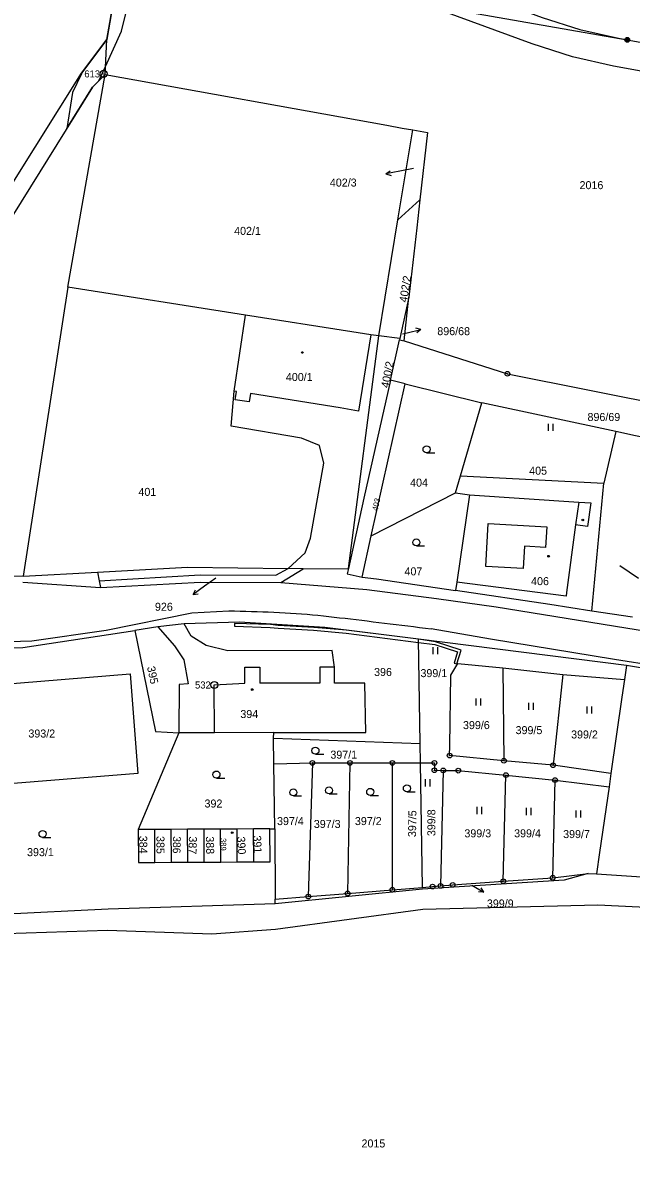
# Model space of a CAD drawing. Extents: x -504988 to -494607, y -1123820 to -1114018.
# Drawn here: x -500642.7 to -500513.4, y -1121156.5 to -1120913.2 of the extents above; entities that cross this region are included whole.
import ezdxf

# ---------------------------------------------------------------- set-up
doc = ezdxf.new("R2010")
doc.units = 0
for name, color, linetype in [('Hranice parcel', 7, 'Continuous'), ('Parcelní čísla', 7, 'Continuous'), ('Pop  PČ popisy', 7, 'Continuous'), ('Poz předměty', 7, 'Continuous'), ('Vnitřní kresba', 7, 'Continuous'), ('Věcná břemena k části', 7, 'Continuous'), ('Značky bodu BP', 7, 'Continuous'), ('Značky budov', 7, 'Continuous'), ('Značky kultur', 7, 'Continuous')]:
    doc.layers.add(name, color=color, linetype=linetype)

msp = doc.modelspace()

# ---------------------------------------------------------------- linework, layer by layer
at = {"layer": 'Hranice parcel'}
for p, q in [((-500624.9, -1120916.79), (-500620.47, -1120890.99)), ((-500625.28, -1120924.23), (-500624.9, -1120916.79)), ((-500633.18, -1120969.39), (-500625.28, -1120924.23)), ((-500563.02, -1120955.08), (-500559.87, -1120935.98)), ((-500558.33, -1120950.8), (-500563.02, -1120955.08)), ((-500567.08, -1120979.72), (-500563.02, -1120955.08)), ((-500633.18, -1120969.39), (-500642.71, -1121030.76)), ((-500595.39, -1120975.3), (-500633.18, -1120969.39)), ((-500560.66, -1120971.53), (-500562.61, -1120980.26)), ((-500561.67, -1120980.8), (-500560.66, -1120971.53)), ((-500573.51, -1121029.13), (-500567.08, -1120979.72)), ((-500562.61, -1120980.26), (-500567.08, -1120979.72)), ((-500564.59, -1120989.12), (-500562.69, -1120980.6)), ((-500562.61, -1120980.26), (-500562.69, -1120980.6)), ((-500562.69, -1120980.6), (-500561.67, -1120980.8)), ((-500568.68, -1121022.21), (-500561.45, -1120989.9)), ((-500561.45, -1120989.9), (-500564.59, -1120989.12)), ((-500561.45, -1120989.9), (-500545.17, -1120993.98)), ((-500549.69, -1121009.43), (-500545.17, -1120993.98)), ((-500516.66, -1121000.06), (-500545.17, -1120993.98)), ((-500516.66, -1121000.06), (-500519.27, -1121011)), ((-500550.76, -1121013.08), (-500549.69, -1121009.43)), ((-500549.69, -1121009.43), (-500519.27, -1121011)), ((-500568.68, -1121022.21), (-500550.76, -1121013.08)), ((-500521.79, -1121038.18), (-500519.27, -1121011)), ((-500570.64, -1121031), (-500568.68, -1121022.21)), ((-500642.71, -1121030.76), (-500626.85, -1121029.9)), ((-500583.15, -1121029.22), (-500586.36, -1121029.11)), ((-500583.15, -1121029.22), (-500573.51, -1121029.13)), ((-500513.13, -1121039.51), (-500521.79, -1121038.18)), ((-500614.03, -1121041.57), (-500618.97, -1121042.32)), ((-500608.44, -1121040.9), (-500614.03, -1121041.57)), ((-500558.29, -1121066.33), (-500558.64, -1121044.18)), ((-500514.41, -1121049.75), (-500558.64, -1121044.18)), ((-500540.68, -1121050.26), (-500527.99, -1121051.68)), ((-500540.68, -1121050.26), (-500540.49, -1121070)), ((-500527.99, -1121051.68), (-500530.04, -1121070.93)), ((-500527.99, -1121051.68), (-500514.83, -1121052.7)), ((-500514.41, -1121049.75), (-500514.83, -1121052.7)), ((-500479.4, -1121055.39), (-500514.41, -1121049.75)), ((-500514.83, -1121052.7), (-500515.38, -1121056.46)), ((-500515.38, -1121056.46), (-500517.72, -1121072.72)), ((-500609.57, -1121064.08), (-500618.21, -1121084.59)), ((-500589.43, -1121065.18), (-500589.36, -1121064.01)), ((-500589.37, -1121070.65), (-500589.43, -1121065.18)), ((-500589.43, -1121065.18), (-500558.29, -1121066.33)), ((-500558.22, -1121070.44), (-500558.29, -1121066.33)), ((-500589.37, -1121070.65), (-500581.2, -1121070.43)), ((-500589.21, -1121084.46), (-500589.37, -1121070.65)), ((-500581.2, -1121070.43), (-500582.08, -1121098.84)), ((-500581.2, -1121070.43), (-500573.2, -1121070.45)), ((-500573.2, -1121070.45), (-500573.71, -1121098.17)), ((-500573.2, -1121070.45), (-500564.2, -1121070.45)), ((-500564.2, -1121070.45), (-500558.22, -1121070.44)), ((-500564.19, -1121097.4), (-500564.2, -1121070.45)), ((-500557.81, -1121096.88), (-500558.22, -1121070.44)), ((-500530.04, -1121070.93), (-500540.49, -1121070)), ((-500517.72, -1121072.72), (-500530.04, -1121070.93)), ((-500553.38, -1121072.04), (-500553.95, -1121096.57)), ((-500540.62, -1121095.59), (-500540.07, -1121073.02)), ((-500540.07, -1121073.02), (-500529.61, -1121074.08)), ((-500517.72, -1121072.72), (-500518.13, -1121075.56)), ((-500530.09, -1121094.83), (-500529.61, -1121074.08)), ((-500529.61, -1121074.08), (-500518.13, -1121075.56)), ((-500614.71, -1121084.58), (-500618.21, -1121084.59)), ((-500611.21, -1121084.56), (-500614.71, -1121084.58)), ((-500614.67, -1121091.58), (-500614.71, -1121084.58)), ((-500607.71, -1121084.54), (-500611.21, -1121084.56)), ((-500611.17, -1121091.56), (-500611.21, -1121084.56)), ((-500604.21, -1121084.53), (-500607.71, -1121084.54)), ((-500607.67, -1121091.54), (-500607.71, -1121084.54)), ((-500600.71, -1121084.51), (-500604.21, -1121084.53)), ((-500604.17, -1121091.53), (-500604.21, -1121084.53)), ((-500597.21, -1121084.5), (-500600.71, -1121084.51)), ((-500600.67, -1121091.51), (-500600.71, -1121084.51)), ((-500593.71, -1121084.48), (-500597.21, -1121084.5)), ((-500597.17, -1121091.49), (-500597.21, -1121084.5)), ((-500590.21, -1121084.46), (-500593.71, -1121084.48)), ((-500593.67, -1121091.48), (-500593.71, -1121084.48)), ((-500590.21, -1121084.46), (-500589.21, -1121084.46)), ((-500589.21, -1121084.46), (-500589.1, -1121099.41)), ((-500614.67, -1121091.58), (-500611.17, -1121091.56)), ((-500611.17, -1121091.56), (-500607.67, -1121091.54)), ((-500607.67, -1121091.54), (-500604.17, -1121091.53)), ((-500604.17, -1121091.53), (-500600.67, -1121091.51)), ((-500600.67, -1121091.51), (-500597.17, -1121091.49)), ((-500597.17, -1121091.49), (-500593.67, -1121091.48)), ((-500540.62, -1121095.59), (-500530.09, -1121094.83)), ((-500530.09, -1121094.83), (-500522.58, -1121093.91)), ((-500522.58, -1121093.91), (-500520.79, -1121094.02)), ((-500582.08, -1121098.84), (-500573.71, -1121098.17)), ((-500573.71, -1121098.17), (-500564.19, -1121097.4)), ((-500564.19, -1121097.4), (-500557.81, -1121096.88)), ((-500589.1, -1121099.41), (-500582.08, -1121098.84)), ((-500589.09, -1121100.4), (-500589.1, -1121099.41))]:
    msp.add_line(p, q, dxfattribs=at)
for points in [[(-500764.98, -1120898.32), (-500631.41, -1120885.98), (-500618.26, -1120885.7), (-500608.56, -1120886.58), (-500597.08, -1120888.85), (-500587.15, -1120891.94), (-500532.37, -1120912.08), (-500524.35, -1120914.64), (-500516.15, -1120916.5), (-500513.53, -1120917), (-500396.19, -1120938.19), (-500282.34, -1120959.31), (-500275.43, -1120961.08), (-500094.63, -1121020.61), (-499913.83, -1121080.14), (-499909.87, -1121081.53), (-499905.97, -1121083.08), (-499793.8, -1121130.28), (-499791.45, -1121131.2), (-499789.49, -1121131.83)], [(-500481.13, -1120928.92), (-500517.21, -1120922.4), (-500525.93, -1120920.43), (-500534.44, -1120917.72), (-500589.22, -1120897.57), (-500597.01, -1120895.29), (-500604.68, -1120893.47), (-500611.82, -1120892.14), (-500620.47, -1120890.99)], [(-500687.09, -1121019.98), (-500659.52, -1120970.53), (-500630.25, -1120923.93), (-500624.9, -1120916.79)], [(-500625.28, -1120924.23), (-500627.91, -1120926.88), (-500656.36, -1120972.42), (-500691.37, -1121033.75)], [(-500625.28, -1120924.23), (-500565.35, -1120934.99), (-500562.14, -1120935.57), (-500559.87, -1120935.98)], [(-500559.87, -1120935.98), (-500556.72, -1120936.54), (-500558.33, -1120950.8)], [(-500558.33, -1120950.8), (-500559, -1120956.76), (-500560.66, -1120971.53)], [(-500586.36, -1121029.11), (-500582.7, -1121025.8), (-500581.62, -1121022.67), (-500578.76, -1121006.77), (-500579.7, -1121002.99), (-500583.5, -1121001.43), (-500598.48, -1120998.91), (-500597.83, -1120991.44), (-500595.39, -1120975.3)], [(-500567.08, -1120979.72), (-500568.78, -1120979.52), (-500572.78, -1120978.84), (-500595.39, -1120975.3)], [(-500561.67, -1120980.8), (-500539.74, -1120987.79), (-500504.48, -1120994.81)], [(-500564.59, -1120989.12), (-500570.24, -1121014.17), (-500573.51, -1121029.13)], [(-500506.98, -1121002.13), (-500512.53, -1121000.94), (-500516.66, -1121000.06)], [(-500550.76, -1121013.08), (-500547.79, -1121013.52), (-500550.51, -1121032.04), (-500550.77, -1121033.82)], [(-500689.76, -1121033.75), (-500661.6, -1121029.96), (-500654.12, -1121030.57), (-500642.71, -1121030.76)], [(-500626.85, -1121029.9), (-500607.74, -1121028.86), (-500586.36, -1121029.11)], [(-500626.85, -1121029.9), (-500626.51, -1121031.75), (-500626.25, -1121033.18), (-500605.01, -1121032.04), (-500587.93, -1121032.15), (-500583.15, -1121029.22)], [(-500573.51, -1121029.13), (-500573.77, -1121030.3), (-500570.64, -1121031)], [(-500570.64, -1121031), (-500567.54, -1121031.33), (-500550.77, -1121033.82)], [(-500521.79, -1121038.18), (-500530.71, -1121036.82), (-500550.77, -1121033.82)], [(-500668.7, -1121046.08), (-500642.76, -1121045.92), (-500618.97, -1121042.32)], [(-500618.97, -1121042.32), (-500614.53, -1121063.76), (-500609.57, -1121064.08)], [(-500614.03, -1121041.57), (-500610.51, -1121045.56), (-500608.52, -1121048.57), (-500607.58, -1121053.62), (-500609.52, -1121053.78), (-500609.57, -1121064.08)], [(-500558.64, -1121044.18), (-500578.56, -1121041.67), (-500596.71, -1121040.56), (-500608.44, -1121040.9)], [(-500589.36, -1121064.01), (-500569.85, -1121063.98), (-500570.07, -1121053.48), (-500576.51, -1121053.48), (-500576.51, -1121050.07), (-500576.97, -1121046.59), (-500599.18, -1121046.66), (-500603.8, -1121045.48), (-500606.96, -1121043.54), (-500608.44, -1121040.9)], [(-500540.49, -1121070), (-500552.02, -1121068.9), (-500551.98, -1121066.84), (-500551.73, -1121051.81), (-500550.27, -1121049.31), (-500540.68, -1121050.26)], [(-500619.93, -1121051.53), (-500618.27, -1121072.71), (-500656.27, -1121075.76), (-500657.98, -1121054.66), (-500619.93, -1121051.53)], [(-500589.36, -1121064.01), (-500602.01, -1121064.03), (-500609.57, -1121064.08)], [(-500558.22, -1121070.44), (-500555.24, -1121070.44), (-500555.26, -1121072.01), (-500553.38, -1121072.04)], [(-500553.38, -1121072.04), (-500550.18, -1121072.09), (-500540.07, -1121073.02)], [(-500518.13, -1121075.56), (-500520.13, -1121089.47), (-500520.79, -1121094.02)], [(-500618.21, -1121084.59), (-500618.17, -1121091.59), (-500614.67, -1121091.58)], [(-500593.67, -1121091.48), (-500590.17, -1121091.46), (-500590.21, -1121084.46)], [(-500522.58, -1121093.91), (-500527.7, -1121095.32), (-500557.8, -1121097.25), (-500589.09, -1121100.4)], [(-500553.95, -1121096.57), (-500551.36, -1121096.36), (-500540.62, -1121095.59)], [(-500520.79, -1121094.02), (-500502.67, -1121095.18), (-500501.61, -1121095.25), (-500492.78, -1121096.41), (-500478.14, -1121101.05)], [(-500557.81, -1121096.88), (-500555.64, -1121096.71), (-500553.95, -1121096.57)], [(-500453.45, -1121120.1), (-500479.67, -1121107.66), (-500495.2, -1121102.84), (-500507.32, -1121101.3), (-500520.55, -1121100.68), (-500557.7, -1121101.61), (-500589.02, -1121105.86), (-500602.59, -1121106.82), (-500624.72, -1121106.08), (-500646.33, -1121106.76), (-500655.09, -1121112.32), (-500660.29, -1121119.96), (-500660.92, -1121120.88), (-500668.64, -1121133.13), (-500674.71, -1121144.91), (-500681.84, -1121162.26), (-500689.12, -1121188.67)], [(-500589.09, -1121100.4), (-500624.6, -1121101.5), (-500647.48, -1121102.68)]]:
    msp.add_lwpolyline(points, dxfattribs=at)
at = {"layer": 'Pop  PČ popisy'}
for p, q in [((-500565.56, -1120945.34), (-500564.67, -1120944.66)), ((-500562.61, -1120944.77), (-500565.56, -1120945.34)), ((-500559.67, -1120944.2), (-500562.61, -1120944.77)), ((-500565.56, -1120945.34), (-500564.48, -1120945.64)), ((-500562.07, -1120979.33), (-500561.06, -1120979.08)), ((-500561.06, -1120979.08), (-500558.15, -1120978.35)), ((-500558.15, -1120978.35), (-500559.24, -1120978.11)), ((-500558.15, -1120978.35), (-500559, -1120979.08)), ((-500515.83, -1121028.51), (-500511.9, -1121031.19)), ((-500601.7, -1121031.17), (-500604.12, -1121032.93)), ((-500604.12, -1121032.93), (-500606.55, -1121034.69)), ((-500606.55, -1121034.69), (-500606.03, -1121033.7)), ((-500606.55, -1121034.69), (-500605.44, -1121034.51)), ((-500547.33, -1121096.4), (-500544.73, -1121097.9)), ((-500544.73, -1121097.9), (-500545.85, -1121097.83)), ((-500544.73, -1121097.9), (-500545.35, -1121096.97))]:
    msp.add_line(p, q, dxfattribs=at)
at = {"layer": 'Poz předměty'}
for p, q in [((-500627.14, -1120897.09), (-500514.25, -1120916.84)), ((-500514.25, -1120916.84), (-500396.18, -1120938.19))]:
    msp.add_line(p, q, dxfattribs=at)
for radius in [0.5, 0.4, 0.3, 0.2, 0.1]:
    msp.add_circle((-500514.25, -1120916.84), radius, dxfattribs=at)
at = {"layer": 'Vnitřní kresba'}
for p, q in [((-500568.78, -1120979.52), (-500571.38, -1120995.7)), ((-500597.32, -1120991.52), (-500597.83, -1120991.44)), ((-500597.6, -1120993.28), (-500597.32, -1120991.52)), ((-500594.61, -1120993.76), (-500597.6, -1120993.28)), ((-500594.34, -1120992), (-500594.61, -1120993.76)), ((-500575.32, -1120995), (-500594.34, -1120992)), ((-500571.38, -1120995.7), (-500575.32, -1120995)), ((-500547.79, -1121013.52), (-500524.57, -1121015.06)), ((-500524.57, -1121015.06), (-500525.24, -1121019.87)), ((-500524.57, -1121015.06), (-500522, -1121015.23)), ((-500522, -1121015.23), (-500522.71, -1121020.2)), ((-500544.3, -1121028.74), (-500543.82, -1121019.61)), ((-500543.82, -1121019.61), (-500531.39, -1121020.27)), ((-500531.39, -1121020.27), (-500531.63, -1121024.67)), ((-500525.24, -1121019.87), (-500527.16, -1121034.25)), ((-500522.71, -1121020.2), (-500525.24, -1121019.87)), ((-500536.14, -1121024.43), (-500536.39, -1121029.16)), ((-500531.63, -1121024.67), (-500536.14, -1121024.43)), ((-500588.98, -1121030.59), (-500586.36, -1121029.11)), ((-500536.39, -1121029.16), (-500544.3, -1121028.74)), ((-500642.76, -1121032.04), (-500626.25, -1121033.18)), ((-500626.51, -1121031.75), (-500605.06, -1121030.47)), ((-500605.06, -1121030.47), (-500588.98, -1121030.59)), ((-500587.93, -1121032.15), (-500569.64, -1121033.58)), ((-500527.26, -1121035.03), (-500550.51, -1121032.04)), ((-500569.64, -1121033.58), (-500554.83, -1121035.49)), ((-500527.16, -1121034.25), (-500527.26, -1121035.03)), ((-500554.83, -1121035.49), (-500542.14, -1121037.31)), ((-500542.14, -1121037.31), (-500514.53, -1121041.74)), ((-500625.05, -1121042.22), (-500606.8, -1121038.58)), ((-500606.8, -1121038.58), (-500598.97, -1121038.11)), ((-500640.83, -1121044.49), (-500625.05, -1121042.22)), ((-500543.34, -1121044.15), (-500555.91, -1121041.96)), ((-500514.53, -1121041.74), (-500462.1, -1121050.16)), ((-500655.7, -1121044.96), (-500640.83, -1121044.49)), ((-500516.96, -1121048.51), (-500543.34, -1121044.15)), ((-500463.1, -1121056.99), (-500516.96, -1121048.51)), ((-500595.54, -1121053.49), (-500595.54, -1121050.12)), ((-500595.54, -1121050.12), (-500592.4, -1121050.12)), ((-500592.4, -1121050.12), (-500592.4, -1121053.49)), ((-500602.04, -1121053.89), (-500595.54, -1121053.49)), ((-500602.01, -1121064.03), (-500602.04, -1121053.89))]:
    msp.add_line(p, q, dxfattribs=at)
for points in [[(-500598.97, -1121038.11), (-500597.77, -1121038.14), (-500596.55, -1121038.18), (-500595.35, -1121038.21), (-500594.15, -1121038.25), (-500592.94, -1121038.28), (-500591.75, -1121038.33), (-500590.56, -1121038.38), (-500589.36, -1121038.43), (-500588.18, -1121038.49), (-500587, -1121038.55), (-500585.82, -1121038.62), (-500584.65, -1121038.7), (-500583.49, -1121038.79), (-500582.32, -1121038.88), (-500581.17, -1121038.99), (-500580.03, -1121039.09), (-500578.86, -1121039.21), (-500577.72, -1121039.33), (-500576.57, -1121039.46), (-500575.4, -1121039.59), (-500574.24, -1121039.73), (-500573.08, -1121039.86), (-500571.89, -1121040.01), (-500570.71, -1121040.15), (-500569.52, -1121040.29), (-500568.3, -1121040.44), (-500567.09, -1121040.59), (-500565.88, -1121040.74), (-500564.64, -1121040.89), (-500563.41, -1121041.04), (-500562.17, -1121041.19), (-500560.91, -1121041.35), (-500559.67, -1121041.5), (-500558.42, -1121041.65), (-500557.16, -1121041.81), (-500555.91, -1121041.96)], [(-500576.51, -1121050.07), (-500579.58, -1121050.07), (-500579.58, -1121053.48), (-500592.4, -1121053.49)]]:
    msp.add_lwpolyline(points, dxfattribs=at)
at = {"layer": 'Věcná břemena k části'}
for points in [[(-500615.68, -1120873.77), (-500618.62, -1120885.71), (-500619.94, -1120891.06), (-500621.72, -1120898.29), (-500624.9, -1120916.79), (-500630.25, -1120923.93), (-500630.31, -1120924.03), (-500632.17, -1120928.06), (-500633.41, -1120935.69), (-500627.91, -1120926.88), (-500626.62, -1120925.58), (-500625.19, -1120922.48), (-500621.74, -1120915), (-500615.98, -1120891.59), (-500614.61, -1120886.03), (-500611.93, -1120875.15), (-500610.37, -1120871.36), (-500580.9, -1120800), (-500585.23, -1120800), (-500614.53, -1120870.98)], [(-500597.77, -1121041.42), (-500590.15, -1121041.67), (-500588.5, -1121041.85), (-500580.96, -1121042.27), (-500573.98, -1121042.87), (-500558.63, -1121044.85), (-500555.15, -1121045.3), (-500550.32, -1121046.87), (-500551.07, -1121049.24), (-500550.5, -1121049.42), (-500549.56, -1121046.48), (-500555.01, -1121044.71), (-500558.64, -1121044.18), (-500573.92, -1121042.27), (-500580.92, -1121041.67), (-500588.45, -1121041.25), (-500590.11, -1121041.07), (-500597.75, -1121040.82)]]:
    msp.add_lwpolyline(points, close=True, dxfattribs=at)
at = {"layer": 'Značky bodu BP'}
for centre, radius in [((-500625.58, -1120924.08), 0.75), ((-500625.58, -1120924.08), 0.03), ((-500539.74, -1120987.79), 0.5), ((-500539.74, -1120987.79), 0.0303), ((-500602.04, -1121053.89), 0.75), ((-500602.04, -1121053.89), 0.03), ((-500552.02, -1121068.9), 0.5), ((-500552.02, -1121068.9), 0.0303), ((-500581.2, -1121070.43), 0.5), ((-500581.2, -1121070.43), 0.0303), ((-500573.2, -1121070.45), 0.5), ((-500573.2, -1121070.45), 0.0303), ((-500564.2, -1121070.45), 0.5), ((-500564.2, -1121070.45), 0.0303), ((-500555.26, -1121072.01), 0.5), ((-500555.24, -1121070.44), 0.5), ((-500555.24, -1121070.44), 0.0303), ((-500553.38, -1121072.04), 0.5), ((-500540.49, -1121070), 0.5), ((-500540.49, -1121070), 0.0303), ((-500530.04, -1121070.93), 0.5), ((-500530.04, -1121070.93), 0.0303), ((-500555.26, -1121072.01), 0.0303), ((-500553.38, -1121072.04), 0.0303), ((-500550.18, -1121072.09), 0.5), ((-500550.18, -1121072.09), 0.0303), ((-500540.07, -1121073.02), 0.5), ((-500540.07, -1121073.02), 0.0303), ((-500529.61, -1121074.08), 0.5), ((-500529.61, -1121074.08), 0.0303), ((-500551.36, -1121096.36), 0.5), ((-500540.62, -1121095.59), 0.5), ((-500540.62, -1121095.59), 0.0303), ((-500530.09, -1121094.83), 0.5), ((-500530.09, -1121094.83), 0.0303), ((-500573.71, -1121098.17), 0.5), ((-500573.71, -1121098.17), 0.0303), ((-500564.19, -1121097.4), 0.5), ((-500564.19, -1121097.4), 0.0303), ((-500555.64, -1121096.71), 0.5), ((-500555.64, -1121096.71), 0.0303), ((-500553.95, -1121096.57), 0.5), ((-500553.95, -1121096.57), 0.0303), ((-500551.36, -1121096.36), 0.0303), ((-500582.08, -1121098.84), 0.5), ((-500582.08, -1121098.84), 0.0303)]:
    msp.add_circle(centre, radius, dxfattribs=at)
at = {"layer": 'Značky budov'}
for centre in [(-500583.34, -1120983.26), (-500523.72, -1121018.84), (-500530.99, -1121026.53), (-500593.99, -1121054.86), (-500598.24, -1121085.27)]:
    msp.add_circle(centre, 0.175, dxfattribs=at)
at = {"layer": 'Značky kultur'}
for p, q in [((-500530.98, -1120999.91), (-500530.98, -1120998.41)), ((-500529.98, -1120999.91), (-500529.98, -1120998.41)), ((-500556.92, -1121004.58), (-500555.17, -1121004.58)), ((-500559.09, -1121024.35), (-500557.34, -1121024.35)), ((-500555.55, -1121047.34), (-500555.55, -1121045.84)), ((-500554.55, -1121047.34), (-500554.55, -1121045.84)), ((-500546.37, -1121058.23), (-500546.37, -1121056.73)), ((-500545.37, -1121058.23), (-500545.37, -1121056.73)), ((-500535.16, -1121059.19), (-500535.16, -1121057.69)), ((-500534.16, -1121059.19), (-500534.16, -1121057.69)), ((-500522.78, -1121059.94), (-500522.78, -1121058.44)), ((-500521.78, -1121059.94), (-500521.78, -1121058.44)), ((-500580.54, -1121068.59), (-500578.79, -1121068.59)), ((-500601.59, -1121073.67), (-500599.84, -1121073.67)), ((-500557.15, -1121075.43), (-500557.15, -1121073.93)), ((-500556.15, -1121075.43), (-500556.15, -1121073.93)), ((-500585.23, -1121077.46), (-500583.48, -1121077.46)), ((-500577.65, -1121077.03), (-500575.9, -1121077.03)), ((-500568.9, -1121077.35), (-500567.15, -1121077.35)), ((-500561.11, -1121076.6), (-500559.36, -1121076.6)), ((-500546.15, -1121081.3), (-500546.15, -1121079.8)), ((-500545.15, -1121081.3), (-500545.15, -1121079.8)), ((-500535.69, -1121081.52), (-500535.69, -1121080.02)), ((-500534.69, -1121081.52), (-500534.69, -1121080.02)), ((-500525.13, -1121082.05), (-500525.13, -1121080.55)), ((-500524.13, -1121082.05), (-500524.13, -1121080.55)), ((-500638.55, -1121086.28), (-500636.8, -1121086.28))]:
    msp.add_line(p, q, dxfattribs=at)
for centre in [(-500556.92, -1121003.83), (-500559.09, -1121023.6), (-500580.54, -1121067.84), (-500601.59, -1121072.92), (-500585.23, -1121076.71), (-500577.65, -1121076.28), (-500568.9, -1121076.6), (-500561.11, -1121075.85), (-500638.55, -1121085.53)]:
    msp.add_circle(centre, 0.75, dxfattribs=at)

# ---------------------------------------------------------------- texts
at = {"layer": 'Parcelní čísla'}
for s, p in [('402/3', (-500577.48, -1120948.01)), ('2016', (-500524.4, -1120948.56)), ('402/1', (-500597.83, -1120958.27)), ('896/68', (-500554.64, -1120979.58)), ('400/1', (-500586.83, -1120989.31)), ('896/69', (-500522.71, -1120997.81)), ('405', (-500535.11, -1121009.22)), ('404', (-500560.42, -1121011.75)), ('401', (-500618.17, -1121013.72)), ('407', (-500561.62, -1121030.6)), ('406', (-500534.7, -1121032.68)), ('926', (-500614.66, -1121038.12)), ('396', (-500568.08, -1121051.98)), ('399/1', (-500558.22, -1121052.22)), ('394', (-500596.51, -1121060.91)), ('399/6', (-500549.18, -1121063.26)), ('393/2', (-500641.56, -1121065.05)), ('399/5', (-500538, -1121064.33)), ('399/2', (-500526.2, -1121065.25)), ('397/1', (-500577.37, -1121069.54)), ('392', (-500604.12, -1121079.92)), ('397/4', (-500588.71, -1121083.65)), ('397/3', (-500580.89, -1121084.26)), ('397/2', (-500572.16, -1121083.65)), ('399/3', (-500548.88, -1121086.25)), ('399/4', (-500538.31, -1121086.25)), ('399/7', (-500527.89, -1121086.41)), ('393/1', (-500641.85, -1121090.25)), ('399/9', (-500544.1, -1121101.15)), ('2015', (-500570.75, -1121152.13))]:
    msp.add_text(s, height=1.7, dxfattribs=at).set_placement(p)
for s, height, rotation, p in [('402/2', 1.7, 81, (-500561.07, -1120972.71)), ('400/2', 1.7, 79, (-500564.96, -1120990.9)), ('403', 1.2, 77, (-500567.34, -1121016.97)), ('395', 1.7, 282, (-500616.36, -1121050.1)), ('397/5', 1.7, 89, (-500559.17, -1121086.22)), ('399/8', 1.7, 90, (-500555.05, -1121086)), ('384', 1.7, 271, (-500618.02, -1121085.93)), ('385', 1.7, 270, (-500614.34, -1121085.98)), ('386', 1.646, 269, (-500610.81, -1121086)), ('387', 1.7, 268, (-500607.42, -1121086.03)), ('388', 1.7, 271, (-500603.83, -1121086.05)), ('391', 1.7, 273, (-500593.81, -1121085.9)), ('389', 1.2, 270, (-500600.72, -1121086.41)), ('390', 1.7, 273, (-500597.21, -1121086.13))]:
    msp.add_text(s, height=height, rotation=rotation, dxfattribs=at).set_placement(p)
at = {"layer": 'Značky bodu BP'}
for s, p in [('613', (-500629.68, -1120924.83)), ('532', (-500606.14, -1121054.64))]:
    msp.add_text(s, height=1.5, dxfattribs=at).set_placement(p)

doc.saveas('drawing.dxf')
